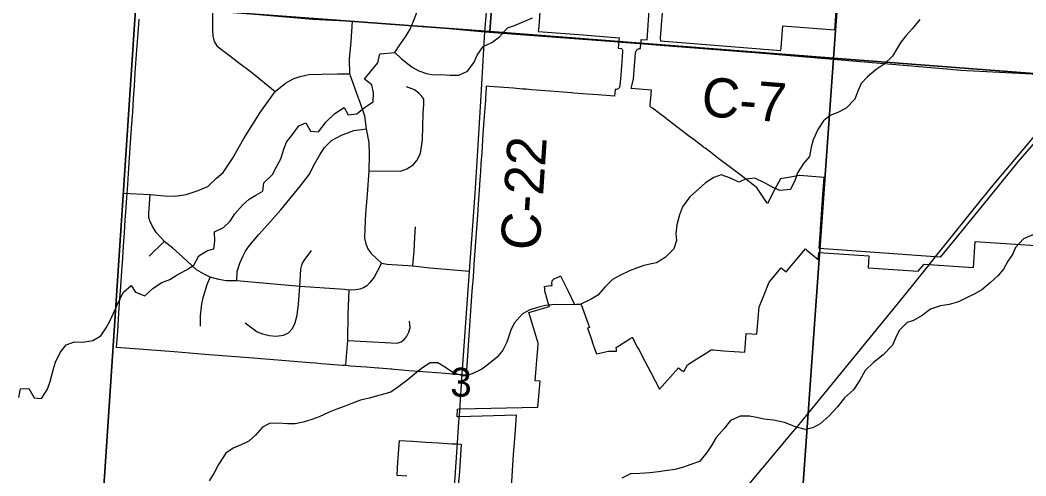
# Model space of a CAD drawing. Extents: x 0 to 34, y 0 to 22.
# Drawn here: x 5 to 6.46, y 15.435 to 16.096 of the extents above; entities that cross this region are included whole.
import ezdxf

# ---------------------------------------------------------------- set-up
doc = ezdxf.new("R2010")
doc.units = 0
for name, color, linetype in [('GM_X_Corporation', 7, 'Continuous'), ('GM_X_County_Road', 7, 'Continuous'), ('GM_X_County_Road_Text', 7, 'Continuous'), ('GM_X_Minor_River', 7, 'Continuous'), ('GM_X_Section_Text', 7, 'Continuous'), ('GM_X_Township_Road', 7, 'Continuous')]:
    doc.layers.add(name, color=color, linetype=linetype)

msp = doc.modelspace()

# ---------------------------------------------------------------- linework, layer by layer
at = {"layer": 'GM_X_Corporation'}
for points in [[(5.2498, 17.1302), (5.7559, 17.0921), (5.682, 16.08), (5.1838, 16.1166)], [(5.7559, 17.0921), (6.2535, 17.0548), (6.1806, 16.0412), (5.682, 16.08)], [(6.2535, 17.0548), (6.7642, 17.0207), (6.6929, 16.0021), (6.1806, 16.0412)], [(4.1846, 16.1905), (4.6827, 16.1525), (5.1682, 16.119), (5.1019, 15.1206), (4.1115, 15.1948)], [(5.1682, 16.119), (5.1838, 16.1166), (5.682, 16.08), (6.1806, 16.0412), (6.1096, 15.0446), (5.1019, 15.1206)], [(6.1806, 16.0412), (6.6929, 16.0021), (7.2018, 15.9686), (7.1441, 14.9641), (6.1096, 15.0446)]]:
    msp.add_lwpolyline(points, close=True, dxfattribs=at)
for points in [[(5.9333, 16.1266), (5.9292, 16.07), (5.9293, 16.0661), (6.1044, 16.0524), (6.1048, 16.0562), (6.1071, 16.0879), (6.1448, 16.085), (6.1826, 16.082), (6.1929, 16.2236)], [(5.7565, 16.1362), (5.7527, 16.0871), (5.7522, 16.0799), (5.8174, 16.0748), (5.8694, 16.0708), (5.8691, 16.0668), (5.869, 16.0651), (5.8683, 16.0557), (5.8728, 16.0553), (5.8735, 16.0545), (5.874, 16.0535), (5.8743, 16.0525), (5.8745, 16.0515), (5.8745, 16.0504), (5.8718, 16.0163), (5.8707, 16.0015), (5.8705, 16.0003), (5.8701, 15.9992), (5.8695, 15.9982), (5.8688, 15.9973), (5.8679, 15.9966), (5.8669, 15.996), (5.8658, 15.9956), (5.8647, 15.9954), (5.8635, 15.9954), (5.8628, 15.9859), (5.8387, 15.9878), (5.8231, 15.989), (5.8038, 15.9905), (5.8003, 15.9908), (5.7821, 15.9922), (5.7689, 15.9933), (5.7557, 15.9943), (5.7424, 15.9953), (5.7345, 15.9959), (5.7292, 15.9963), (5.716, 15.9974), (5.6814, 16), (5.6767, 16.0004), (5.6764, 15.9958), (5.6762, 15.9932), (5.6753, 15.9801), (5.6737, 15.957), (5.6719, 15.9315), (5.67, 15.9038), (5.6689, 15.8883), (5.6681, 15.8768), (5.6668, 15.8579), (5.6667, 15.8562), (5.6653, 15.8365), (5.6637, 15.8134), (5.6587, 15.7422), (5.658, 15.732), (5.657, 15.7172), (5.6567, 15.7142), (5.6567, 15.7138), (5.6559, 15.7027), (5.6475, 15.5809), (5.6418, 15.5814), (5.6361, 15.5818), (5.6338, 15.582), (5.6174, 15.5833), (5.5784, 15.5864), (5.5644, 15.5875), (5.5539, 15.5884), (5.5429, 15.5893), (5.5398, 15.5895), (5.5383, 15.5896), (5.5325, 15.5901), (5.5209, 15.591), (5.5196, 15.5911), (5.508, 15.592), (5.5021, 15.5925), (5.4794, 15.5943), (5.4794, 15.5943), (5.4727, 15.5949), (5.4681, 15.5952), (5.4369, 15.5977), (5.4286, 15.5984), (5.4206, 15.599), (5.3857, 15.6018), (5.362, 15.6037), (5.3495, 15.6047), (5.3389, 15.6056), (5.3, 15.6087), (5.2682, 15.6112), (5.2236, 15.6148), (5.1402, 15.6214), (5.1418, 15.6444), (5.1436, 15.6708), (5.145, 15.6924), (5.1462, 15.7094), (5.1463, 15.7109), (5.1472, 15.7246), (5.1482, 15.7392), (5.1486, 15.7438), (5.1502, 15.768), (5.1511, 15.7817), (5.1515, 15.7873), (5.1528, 15.8069), (5.1531, 15.8112), (5.155, 15.839), (5.1558, 15.8504), (5.1579, 15.8816), (5.16, 15.9114), (5.1619, 15.9393), (5.1635, 15.9631), (5.1648, 15.982), (5.1661, 16.0009), (5.1673, 16.0198), (5.1687, 16.0402), (5.1696, 16.0526), (5.1704, 16.0652), (5.1713, 16.0771), (5.1727, 16.0975)], [(6.4731, 15.9197), (6.4483, 15.8905), (6.4462, 15.888), (6.3918, 15.8215), (6.3555, 15.7771), (6.3352, 15.7524), (6.3283, 15.7529), (6.1597, 15.765), (6.1607, 15.7791), (6.1616, 15.7911), (6.1617, 15.7933), (6.1628, 15.8075), (6.1638, 15.8216), (6.1653, 15.8429), (6.1671, 15.8681), (6.1492, 15.8694), (6.1312, 15.8707), (6.1236, 15.8693), (6.1182, 15.8685), (6.1036, 15.8659), (6.0956, 15.8508), (6.0846, 15.83), (6.0783, 15.8395), (6.0689, 15.8537), (6.0684, 15.8541), (6.0551, 15.8642), (6.0527, 15.866), (6.0445, 15.8722), (6.0291, 15.8839), (6.0144, 15.895), (6.013, 15.8962), (6.0124, 15.8966), (6.0072, 15.9005), (6.0019, 15.9046), (5.9942, 15.9104), (5.9926, 15.9116), (5.9913, 15.9126), (5.9848, 15.9175), (5.9808, 15.9206), (5.9773, 15.9233), (5.9767, 15.9237), (5.9763, 15.924), (5.9702, 15.9286), (5.9596, 15.9367), (5.9491, 15.9447), (5.9385, 15.9527), (5.9377, 15.9534), (5.9333, 15.9567), (5.9309, 15.9585), (5.928, 15.9607), (5.9181, 15.9683), (5.9161, 15.9697), (5.9145, 15.971), (5.9145, 15.9712), (5.9147, 15.9732), (5.9154, 15.9833), (5.9163, 15.9946), (5.9044, 15.9955), (5.887, 15.9969), (5.8884, 16.0028), (5.8904, 16.0112), (5.8924, 16.0362), (5.8934, 16.0489), (5.8935, 16.05), (5.8939, 16.051), (5.8943, 16.0519), (5.895, 16.0528), (5.8957, 16.0535), (5.8966, 16.0541), (5.8975, 16.0546), (5.8984, 16.0549), (5.8995, 16.055), (5.9005, 16.055), (5.9011, 16.0626), (5.9013, 16.0653), (5.9015, 16.0683), (5.91, 16.0676), (5.914, 16.1242)], [(5.7131, 15.4186), (5.7164, 15.4659), (5.7184, 15.4944), (5.7204, 15.5228), (5.6375, 15.5206), (5.6342, 15.5206), (5.635, 15.5319), (5.6383, 15.532), (5.7517, 15.5345), (5.755, 15.5723), (5.7476, 15.573), (5.7509, 15.6144), (5.7513, 15.6189), (5.752, 15.6273), (5.7409, 15.6644), (5.7386, 15.6721), (5.7648, 15.6799), (5.7676, 15.6807), (5.7682, 15.6809), (5.7662, 15.6876), (5.7631, 15.698), (5.7623, 15.7012), (5.7618, 15.7044), (5.7615, 15.7065), (5.7611, 15.7099), (5.7636, 15.7102), (5.7667, 15.7106), (5.7699, 15.711), (5.7724, 15.7113), (5.772, 15.7144), (5.7719, 15.7155), (5.7721, 15.7166), (5.7724, 15.7177), (5.7729, 15.7187), (5.7736, 15.7196), (5.7744, 15.7204), (5.7754, 15.721), (5.7764, 15.7215), (5.7797, 15.7227), (5.7828, 15.7242), (5.7844, 15.725), (5.7953, 15.7031), (5.8049, 15.6837), (5.8142, 15.6839), (5.8143, 15.6836), (5.8263, 15.6501), (5.8237, 15.6492), (5.8256, 15.6439), (5.8274, 15.6385), (5.8293, 15.6329), (5.8315, 15.6263), (5.8361, 15.6128), (5.8364, 15.6119), (5.8542, 15.6158), (5.8656, 15.6158), (5.8655, 15.6185), (5.8653, 15.6211), (5.8667, 15.622), (5.8689, 15.6234), (5.8757, 15.6278), (5.8852, 15.6338), (5.8882, 15.6358), (5.8886, 15.636), (5.8963, 15.6213), (5.8979, 15.6184), (5.9067, 15.6015), (5.9155, 15.5847), (5.9281, 15.5607), (5.9557, 15.5916), (5.9581, 15.5896), (5.9606, 15.5878), (5.9633, 15.5862), (5.9689, 15.5961), (5.9824, 15.6048), (5.9948, 15.6127), (5.9962, 15.6135), (6.0031, 15.618), (6.0064, 15.6177), (6.0215, 15.6165), (6.0366, 15.6154), (6.0517, 15.6142), (6.0538, 15.6416), (6.0621, 15.6409), (6.0695, 15.6404), (6.0703, 15.6517), (6.0726, 15.6804), (6.0788, 15.6952), (6.0874, 15.7159), (6.1048, 15.7368), (6.1048, 15.7368), (6.1118, 15.731), (6.1398, 15.7645), (6.1421, 15.7625), (6.1585, 15.7489), (6.1592, 15.7592), (6.232, 15.7541), (6.2307, 15.737), (6.3037, 15.7318), (6.3123, 15.7423), (6.3192, 15.7418), (6.3836, 15.7371), (6.3863, 15.7749), (6.5329, 15.7652)], [(5.5614, 15.4344), (5.5471, 15.4352), (5.5479, 15.4462), (5.5485, 15.4554), (5.5489, 15.4606), (5.5494, 15.4674), (5.5507, 15.4862), (5.5696, 15.485), (5.5697, 15.485), (5.5887, 15.4839), (5.6078, 15.4828), (5.6267, 15.4816), (5.6347, 15.4812), (5.6404, 15.4808), (5.6393, 15.465), (5.6376, 15.4413), (5.6361, 15.4203)]]:
    msp.add_lwpolyline(points, dxfattribs=at)
at = {"layer": 'GM_X_County_Road'}
for p, q in [((6.3195, 15.7413), (6.3283, 15.7523)), ((5.6376, 15.5226), (5.6417, 15.5825)), ((5.6369, 15.5127), (5.6376, 15.5226)), ((5.6348, 15.4828), (5.6369, 15.5127))]:
    msp.add_line(p, q, dxfattribs=at)
for points in [[(5.6634, 15.8909), (5.6689, 15.9788), (5.6747, 16.0795), (5.6905, 16.2707), (5.7013, 16.4575), (5.7172, 16.6298), (5.7256, 16.7302), (5.7283, 16.7596), (5.7298, 16.7876), (5.7322, 16.8162), (5.7475, 17.0234), (5.7594, 17.1888), (5.762, 17.2294), (5.7677, 17.3098), (5.7719, 17.366), (5.7758, 17.4155), (5.7802, 17.4822), (5.7888, 17.6044)], [(4.2246, 16.1884), (4.2391, 16.1866), (4.3591, 16.1786), (4.5586, 16.1626), (4.6445, 16.1573), (4.6875, 16.154), (4.8399, 16.1412), (4.9672, 16.1321), (5.2793, 16.1102), (5.4249, 16.0979), (5.4818, 16.0947), (5.5374, 16.0903), (5.5601, 16.0891), (5.5855, 16.0875), (5.6227, 16.0842), (5.6747, 16.0795), (5.8624, 16.0651), (5.8664, 16.0647)], [(5.8664, 16.0647), (5.9118, 16.0613), (5.9168, 16.0609)], [(5.9168, 16.0609), (6.0471, 16.0509), (6.0534, 16.0504), (6.0669, 16.0492), (6.3448, 16.0254), (6.3457, 16.0254), (6.3647, 16.0237), (6.5064, 16.0163), (6.5453, 16.0133), (6.5533, 16.0128)], [(6.3283, 15.7523), (6.3975, 15.8384), (6.4005, 15.8421), (6.4098, 15.8539), (6.5194, 15.9836), (6.5453, 16.0133), (6.556, 16.0261)], [(5.6417, 15.5825), (5.6521, 15.732), (5.6605, 15.8445), (5.6634, 15.8909)], [(5.7654, 15.0689), (5.9431, 15.2845), (5.9472, 15.2891), (5.956, 15.2997), (6.0772, 15.4457), (6.0779, 15.4466), (6.0901, 15.461), (6.1222, 15.4992), (6.1287, 15.5069), (6.1349, 15.5146), (6.2818, 15.6943), (6.3195, 15.7413)], [(5.6061, 15.0833), (5.609, 15.1242), (5.6198, 15.2751), (5.625, 15.3412), (5.6348, 15.4828)]]:
    msp.add_lwpolyline(points, dxfattribs=at)
at = {"layer": 'GM_X_Minor_River'}
for points in [[(5.5438, 16.0494), (5.55, 16.0589), (5.5603, 16.0736), (5.5661, 16.0834), (5.5712, 16.0947), (5.5759, 16.1072)], [(6.3061, 16.0973), (6.295, 16.0838), (6.2862, 16.074), (6.2785, 16.0642), (6.2723, 16.0544), (6.2661, 16.0442), (6.2539, 16.0326), (6.2424, 16.0247), (6.2298, 16.0138), (6.2206, 16.0041), (6.216, 15.9931), (6.2117, 15.9818), (6.199, 15.9686), (6.1868, 15.9623), (6.1758, 15.9579), (6.1663, 15.95), (6.1578, 15.9375), (6.1512, 15.9224), (6.148, 15.9118), (6.146, 15.8986), (6.1372, 15.8884), (6.1283, 15.8749), (6.1248, 15.8643), (6.1182, 15.8503), (6.1027, 15.8489), (6.0921, 15.854), (6.0804, 15.8602), (6.0665, 15.8668), (6.0528, 15.8654), (6.0433, 15.8609), (6.0313, 15.8671), (6.0177, 15.8718), (6.007, 15.8681), (5.9948, 15.8603), (5.9845, 15.8509), (5.9719, 15.8397), (5.9615, 15.8254), (5.9572, 15.8136), (5.9533, 15.7993), (5.952, 15.786), (5.9526, 15.7765), (5.9487, 15.7644), (5.9361, 15.752), (5.9235, 15.7442), (5.914, 15.742), (5.9041, 15.7398), (5.8946, 15.7361), (5.8847, 15.7324), (5.8703, 15.7257), (5.86, 15.7198), (5.8492, 15.7093), (5.8385, 15.6972), (5.829, 15.6912), (5.8141, 15.6842), (5.8012, 15.6832), (5.7766, 15.6834), (5.7626, 15.6821), (5.7527, 15.6799), (5.7398, 15.6759), (5.7291, 15.6699), (5.7172, 15.6564), (5.7122, 15.6465), (5.7063, 15.6288), (5.7005, 15.6174), (5.6925, 15.6073), (5.6798, 15.5968), (5.6703, 15.5897), (5.6562, 15.583), (5.6444, 15.5797), (5.6297, 15.584), (5.6188, 15.5913), (5.6064, 15.5987), (5.5954, 15.5988), (5.5828, 15.5906), (5.5725, 15.5823), (5.5614, 15.5733), (5.5496, 15.5644), (5.5381, 15.5565)], [(5.5438, 16.0494), (5.5536, 16.0402), (5.5689, 16.0279), (5.5787, 16.0229), (5.5901, 16.0186), (5.6003, 16.017), (5.6101, 16.0173), (5.6241, 16.0164), (5.6366, 16.0162), (5.6496, 16.0222), (5.6592, 16.0353), (5.6635, 16.0455), (5.6723, 16.058), (5.6845, 16.0639), (5.6959, 16.0721), (5.7075, 16.0853), (5.7177, 16.0886), (5.7314, 16.0942), (5.7436, 16.0997)], [(5.3536, 15.8602), (5.3662, 15.8721), (5.3728, 15.8842), (5.3783, 15.8951), (5.383, 15.9091), (5.3869, 15.9193), (5.3954, 15.9302), (5.4047, 15.943), (5.4146, 15.947), (5.4216, 15.9351), (5.433, 15.9342), (5.4441, 15.9485), (5.4568, 15.9608), (5.4702, 15.9694), (5.4764, 15.959), (5.489, 15.9604), (5.4997, 15.9697), (5.5123, 15.9779), (5.5132, 15.9908), (5.5107, 16.0022), (5.4999, 16.0107), (5.5099, 16.0231), (5.5192, 16.0344), (5.522, 16.0472), (5.5438, 16.0494)], [(4.9983, 15.5485), (5.0008, 15.5614), (5.0129, 15.5616), (5.0206, 15.5482), (5.0312, 15.5473), (5.0397, 15.5605), (5.0437, 15.5718), (5.0485, 15.59), (5.0516, 15.5998), (5.0583, 15.6141), (5.0671, 15.625), (5.0789, 15.6294), (5.0907, 15.6289), (5.1058, 15.6313), (5.1173, 15.638), (5.125, 15.6496), (5.1305, 15.6594), (5.1383, 15.6772), (5.143, 15.6873), (5.15, 15.7013), (5.1615, 15.7114), (5.1678, 15.7014), (5.1813, 15.6963), (5.1932, 15.7075), (5.2058, 15.7157), (5.2172, 15.7201), (5.2279, 15.7268), (5.2416, 15.7338), (5.2523, 15.7409), (5.2593, 15.7541), (5.2719, 15.7619), (5.2814, 15.7644), (5.2827, 15.7757), (5.2822, 15.789), (5.2951, 15.7953), (5.3051, 15.8047), (5.3117, 15.8152), (5.3228, 15.8276), (5.3324, 15.8365), (5.342, 15.8421), (5.3523, 15.848), (5.3536, 15.8602)], [(6.4698, 15.7848), (6.4565, 15.7788), (6.4446, 15.7661), (6.4403, 15.7562), (6.4338, 15.7464), (6.4272, 15.7351), (6.4191, 15.725), (6.4084, 15.7156), (6.3958, 15.7047), (6.3848, 15.6984), (6.3737, 15.6932), (6.3619, 15.6876), (6.3486, 15.6836), (6.3361, 15.6818), (6.3213, 15.6766), (6.3094, 15.6676), (6.2969, 15.6606), (6.2874, 15.6576), (6.2759, 15.646)], [(6.2759, 15.646), (6.2704, 15.6347), (6.2662, 15.6245), (6.2528, 15.6106), (6.2386, 15.5993), (6.2267, 15.5877), (6.2186, 15.5737), (6.2094, 15.5598), (6.1964, 15.5481), (6.1864, 15.5353), (6.1745, 15.5218), (6.1611, 15.5106), (6.1505, 15.5046), (6.1395, 15.5021), (6.1255, 15.506), (6.1093, 15.5122), (6.0934, 15.5158), (6.0801, 15.5171), (6.0688, 15.5195), (6.0586, 15.5215), (6.0453, 15.5216), (6.0309, 15.5153), (6.022, 15.5037), (6.0105, 15.4905), (6.0036, 15.4788), (5.9967, 15.469), (5.9859, 15.4555), (5.9722, 15.451), (5.9627, 15.4477), (5.9502, 15.4441), (5.9365, 15.4423), (5.9267, 15.4409), (5.9141, 15.4391), (5.8997, 15.4385), (5.8861, 15.4379), (5.8735, 15.4316)], [(5.5381, 15.5565), (5.5065, 15.5476), (5.494, 15.5447), (5.4799, 15.5396), (5.4704, 15.5356), (5.4582, 15.5312), (5.4487, 15.5275), (5.4343, 15.5205), (5.4236, 15.5169), (5.4111, 15.5129), (5.3993, 15.5104), (5.3883, 15.5105), (5.3751, 15.5115), (5.3618, 15.5109), (5.3519, 15.5057), (5.3419, 15.4941), (5.3319, 15.4851), (5.3209, 15.4799), (5.3091, 15.4752), (5.2988, 15.4677), (5.2879, 15.4512), (5.2817, 15.4391), (5.2744, 15.4278)]]:
    msp.add_lwpolyline(points, dxfattribs=at)
at = {"layer": 'GM_X_Township_Road'}
msp.add_line((5.1875, 15.7538), (5.2091, 15.7748), dxfattribs=at)
for points in [[(5.2793, 16.1102), (5.2791, 16.0964), (5.2793, 16.091), (5.2791, 16.081), (5.2797, 16.0734), (5.2815, 16.0651), (5.2856, 16.0591), (5.2925, 16.0537), (5.3039, 16.045), (5.3153, 16.0363), (5.3361, 16.0206), (5.3702, 15.9929)], [(5.4818, 16.0947), (5.48, 16.0647), (5.4778, 16.04), (5.4783, 16.0185), (5.4809, 16.0104), (5.4881, 15.9902), (5.4935, 15.9759), (5.4998, 15.9575), (5.5025, 15.9383), (5.506, 15.9185), (5.5069, 15.9006), (5.506, 15.8778), (5.5037, 15.8433), (5.5012, 15.8158), (5.5002, 15.7934), (5.4999, 15.7797), (5.5019, 15.7717), (5.5047, 15.7645), (5.5098, 15.7578), (5.5244, 15.7434), (5.5329, 15.7421), (5.57, 15.7398), (5.5945, 15.7369), (5.6521, 15.732)], [(5.1497, 15.845), (5.1888, 15.8434), (5.2098, 15.8414), (5.2253, 15.8408), (5.241, 15.843), (5.2585, 15.849), (5.2725, 15.855), (5.2851, 15.8667), (5.2946, 15.8751), (5.3085, 15.8956), (5.325, 15.9247), (5.3483, 15.9622), (5.3702, 15.9929), (5.3853, 16.0046), (5.3962, 16.0112), (5.4066, 16.0147), (5.4189, 16.0173), (5.4386, 16.0179), (5.4608, 16.0185), (5.4783, 16.0185)], [(5.506, 15.8778), (5.5524, 15.8772), (5.5612, 15.8807), (5.5704, 15.8864), (5.5758, 15.8928), (5.581, 15.9029), (5.5842, 15.9227), (5.5852, 15.9615), (5.5861, 15.9738), (5.5858, 15.9805), (5.585, 15.9832), (5.5825, 15.9862), (5.579, 15.9903), (5.5723, 15.9949), (5.561, 15.9993)], [(5.3144, 15.7178), (5.315, 15.7317), (5.319, 15.7436), (5.3233, 15.7532), (5.3273, 15.7608), (5.3332, 15.7691), (5.3468, 15.7853), (5.3594, 15.7999), (5.3787, 15.8208), (5.4068, 15.8557), (5.4199, 15.8726), (5.426, 15.8848), (5.4352, 15.901), (5.4419, 15.9115), (5.4521, 15.9214), (5.4666, 15.9292), (5.4845, 15.9361), (5.5025, 15.9383)], [(5.5244, 15.7434), (5.5184, 15.7313), (5.5138, 15.7233), (5.5076, 15.7153), (5.5035, 15.7108), (5.4985, 15.7079), (5.4933, 15.7059), (5.4875, 15.7047), (5.4779, 15.7045), (5.4707, 15.7054), (5.4063, 15.7097), (5.3144, 15.7178), (5.2993, 15.718), (5.2883, 15.7199), (5.276, 15.7231), (5.2663, 15.7283), (5.256, 15.7341), (5.2427, 15.7464), (5.2311, 15.7571), (5.2211, 15.7658), (5.2091, 15.7748), (5.2098, 15.7748), (5.1978, 15.7874), (5.192, 15.7968), (5.1882, 15.8052), (5.1869, 15.8097), (5.1869, 15.8156), (5.1888, 15.8434)], [(5.57, 15.7398), (5.5721, 15.7609), (5.5732, 15.7813), (5.5738, 15.7963)], [(5.4063, 15.7097), (5.4077, 15.7347), (5.409, 15.7409), (5.4097, 15.7436), (5.4133, 15.7489), (5.4183, 15.7554), (5.4228, 15.7621)], [(5.2618, 15.6521), (5.2621, 15.6672), (5.2637, 15.6844), (5.2663, 15.695), (5.2715, 15.7125), (5.276, 15.7231)], [(5.3266, 15.6569), (5.3442, 15.644), (5.3521, 15.641), (5.3614, 15.6387), (5.3716, 15.6377), (5.3826, 15.639), (5.3894, 15.6426), (5.3949, 15.6483), (5.3987, 15.6553), (5.4022, 15.6683), (5.4043, 15.6841), (5.4063, 15.7097)], [(5.4726, 15.5965), (5.4759, 15.6311), (5.4762, 15.6701), (5.4779, 15.7045)], [(5.4759, 15.6311), (5.5474, 15.6277), (5.5529, 15.6292), (5.5577, 15.6326), (5.5608, 15.6369), (5.5642, 15.6434), (5.5661, 15.6501), (5.5652, 15.6595)]]:
    msp.add_lwpolyline(points, dxfattribs=at)

# ---------------------------------------------------------------- texts
at = {"layer": 'GM_X_County_Road_Text'}
for s, rotation, p in [('C-7', 355.4277, (5.9876, 15.9574)), ('C-22', 86.2318, (5.7538, 15.761))]:
    msp.add_text(s, height=0.05682, rotation=rotation, dxfattribs=at).set_placement(p)
at = {"layer": 'GM_X_Section_Text'}
msp.add_text('3', height=0.0419, rotation=0, dxfattribs=at).set_placement((5.6244, 15.5499))

doc.saveas('drawing.dxf')
